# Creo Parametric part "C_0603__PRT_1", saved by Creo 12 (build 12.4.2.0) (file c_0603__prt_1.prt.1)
Units: Custom; MM, KILOGRAM, SECS

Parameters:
  PTC_WM_ITERATION = "0"
  PTC_WM_VERSION = "-.0"
  PTC_WM_LIFECYCLE_STATE = "In Work"
  PTC_WM_LIFECYCLE = "MO_CADDocument"
  PTC_WM_CREATED_BY = "Maximilian Roepper (Z0017RMS: MO)"
  PTC_WM_CREATED_ON = "18-Sep-26 11:36:42 AM"
  PTC_WM_MODIFIED_BY = "Maximilian Roepper (Z0017RMS: MO)"
  PTC_WM_MODIFIED_ON = "18-Sep-26 11:36:46 AM"
  PDMLINKNUMBER = "PDM000071455157"
  PTC_WM_NAME = "c_0603__prt_1.prt"
  PTC_WM_NUMBER = "PDM000071455157"

Other parameters: WEIGHT, WEIGHT_FACTOR, WEIGHT_ADD, _MASS_TEMP, _DIFF_TEMP, MC_ERRORS, SUPPLIER

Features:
  1. coordinate system
  2. datum plane "PRT_YZ"
  3. datum plane "PRT_XY"
  4. datum plane "PRT_XZ"
  5. coordinate system
  6. datum axis
  7. datum axis
  8. datum axis
  9. coordinate system
  10. imported feature
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
Other named items: PRT, SIEMENS_MO, DRW_VIEW_ORG, PRT_X, PRT_Y, PRT_Z, CS0, ROUGH_GROB

Layers: 00_STD_CSYS-KSYS, 01_STD_PLANES-EBENEN, 02_STD_AXES-ACHSEN, 03_STD_CSYS-KSYS, 24_IMPORT_FEAT-IMPORT_KE

Surfaces: 16 plane, 12 cylinder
